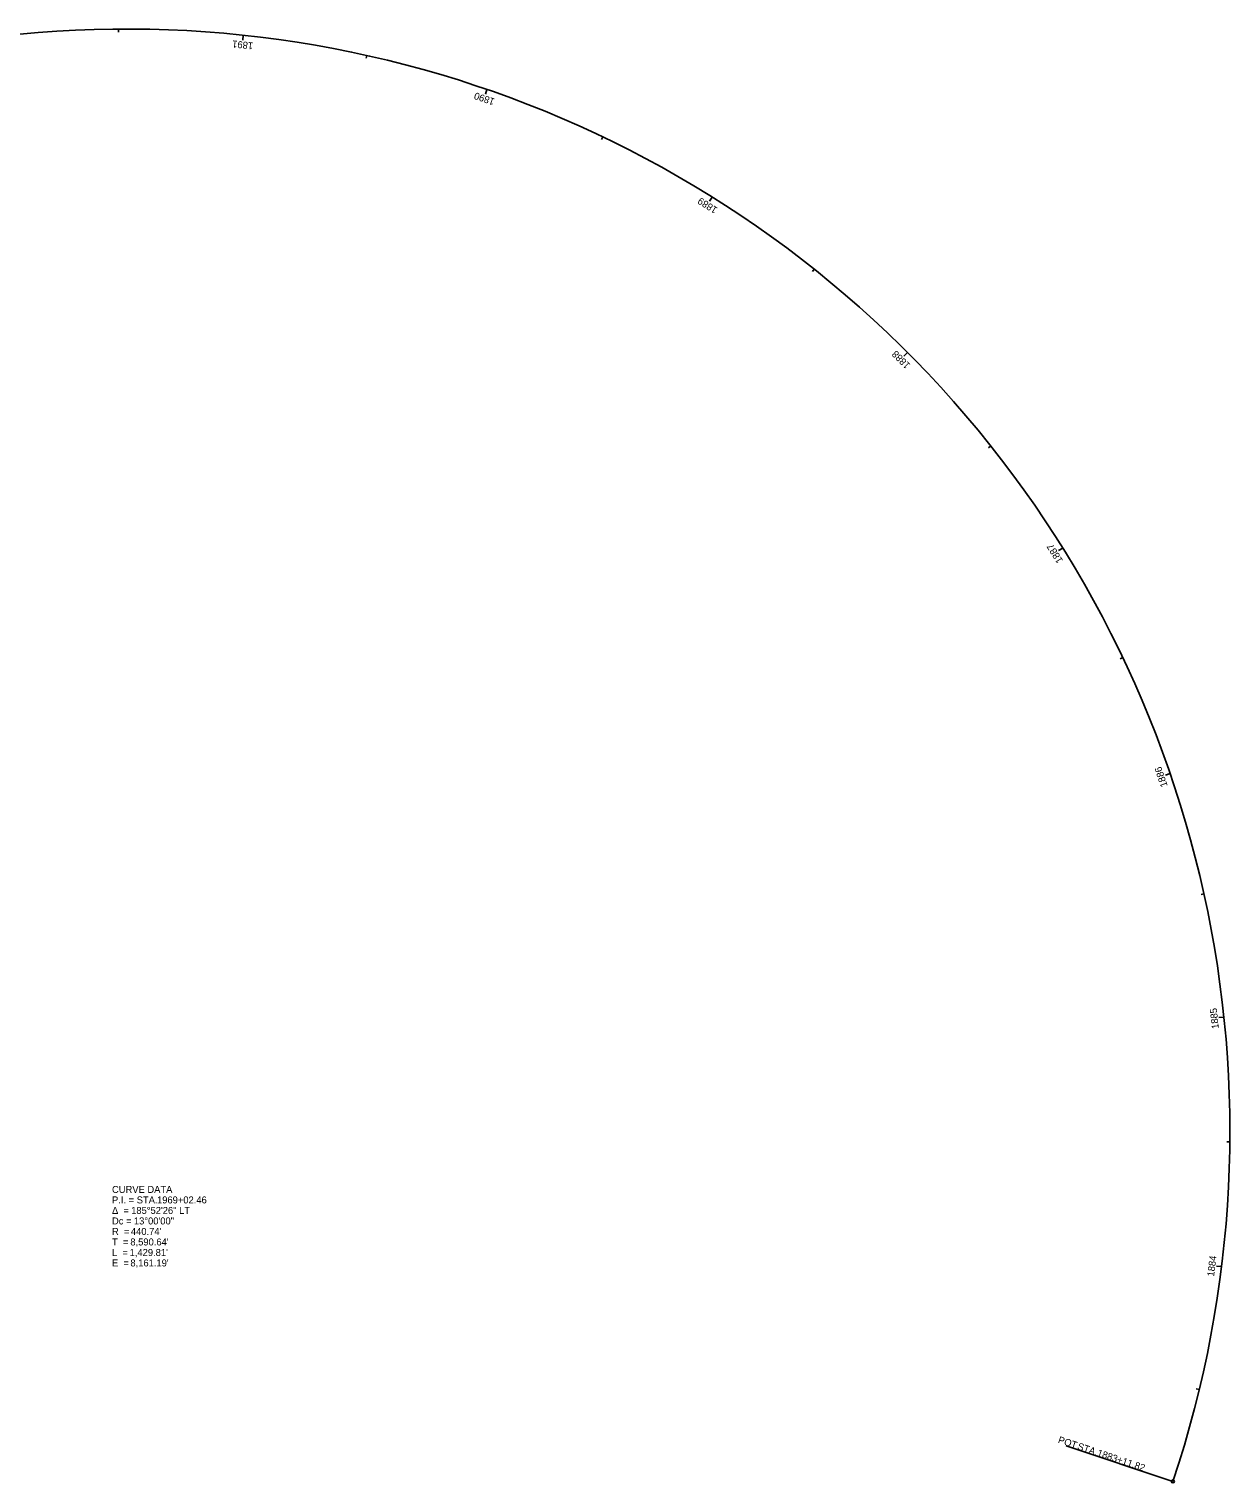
# Model space of a CAD drawing. Extents: x 199397 to 200361, y 391726 to 392499.
# Drawn here: x 199881 to 200361, y 391918 to 392499 of the extents above; entities that cross this region are included whole.
import ezdxf

# ---------------------------------------------------------------- set-up
doc = ezdxf.new("R2010")
doc.units = 0
for name, color, linetype in [('GE_X_Alignment', 7, 'Continuous'), ('RW_X_CL', 7, 'Continuous'), ('SC_Scratch5', 7, 'Continuous'), ('SV_X_Mon_Cells_Found', 7, 'Continuous'), ('SV_X_Mon_Cells_Found_Text', 7, 'Continuous')]:
    doc.layers.add(name, color=color, linetype=linetype)

msp = doc.modelspace()

# ---------------------------------------------------------------- linework, layer by layer
at = {"layer": 'RW_X_CL'}
msp.add_line((200338.25, 391918.25), (200295.58, 391932.53), dxfattribs=at)
msp.add_circle((200338.25, 391918.25), 0.6, dxfattribs=at)
at = {"layer": 'SC_Scratch5'}
msp.add_arc((199920.3, 392058.15), 440.74, 341.49376, 167.36769, dxfattribs=at)
at = {"layer": 'SV_X_Mon_Cells_Found'}
msp.add_arc((199920.3, 392058.15), 440.74, 341.49376, 167.36769, dxfattribs=at)
at = {"layer": 'SV_X_Mon_Cells_Found_Text'}
for p, q in [((199916.79, 392498.87), (199916.8, 392497.67)), ((199966.71, 392496.44), (199966.5, 392494.45)), ((200016.03, 392488.37), (200015.76, 392487.19)), ((200064.11, 392474.76), (200063.46, 392472.87)), ((200110.35, 392455.81), (200109.83, 392454.72)), ((200154.14, 392431.74), (200153.08, 392430.04)), ((200194.93, 392402.86), (200194.19, 392401.93)), ((200232.19, 392369.56), (200230.78, 392368.15)), ((200265.44, 392332.25), (200264.5, 392331.51)), ((200294.25, 392291.42), (200292.55, 392290.36)), ((200318.25, 392247.59), (200317.17, 392247.07)), ((200337.14, 392201.32), (200335.25, 392200.67)), ((200350.67, 392153.22), (200349.5, 392152.96)), ((200358.67, 392103.89), (200356.68, 392103.68)), ((200361.03, 392053.97), (200359.83, 392053.98)), ((200357.72, 392004.11), (200355.73, 392004.35)), ((200348.79, 391954.94), (200347.62, 391955.22))]:
    msp.add_line(p, q, dxfattribs=at)

# ---------------------------------------------------------------- texts
at = {"layer": 'GE_X_Alignment'}
for s, p in [('CURVE DATA', (199914.24, 392033.59)), ('P.I. = STA. ', (199914.24, 392029.39)), ('1969+02.46', (199932.23, 392029.39)), ('Δ  = ', (199914.24, 392025.19)), ('185°52\'26" LT', (199921.89, 392025.19)), ('Dc = ', (199914.24, 392020.99)), ('R  = ', (199914.24, 392016.79)), ("440.74'", (199921.78, 392016.79)), ('13°00\'00"', (199922.99, 392020.99)), ('T  = ', (199914.24, 392012.59)), ("8,590.64'", (199921.56, 392012.59)), ('L  = ', (199914.24, 392008.39)), ("1,429.81'", (199921.28, 392008.39)), ('E  = ', (199914.24, 392004.19)), ("8,161.19'", (199921.59, 392004.19))]:
    msp.add_text(s, height=2.8, dxfattribs=at).set_placement(p)
at = {"layer": 'RW_X_CL'}
for s, p in [('POT', (200292.12, 391933.73)), (' STA. ', (200298.88, 391931.47)), ('1883+11.82', (200307.72, 391928.51))]:
    msp.add_text(s, height=2.8, rotation=341.49376, dxfattribs=at).set_placement(p)
at = {"layer": 'SV_X_Mon_Cells_Found_Text'}
for s, rotation, p in [('1891', 173.95641, (199970.76, 392493.49)), ('1890', 160.9565, (200067.44, 392470.97)), ('1889', 147.9566, (200156.5, 392427.31)), ('1888', 134.95669, (200233.51, 392364.7)), ('1887', 121.95679, (200294.44, 392286.4)), ('1886', 108.95688, (200336.2, 392196.38)), ('1885', 95.95698, (200356.63, 392099.33)), ('1884', 82.95707, (200354.7, 392000.05))]:
    msp.add_text(s, height=2.8, rotation=rotation, dxfattribs=at).set_placement(p)

doc.saveas('drawing.dxf')
